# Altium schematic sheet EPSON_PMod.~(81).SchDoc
size A4
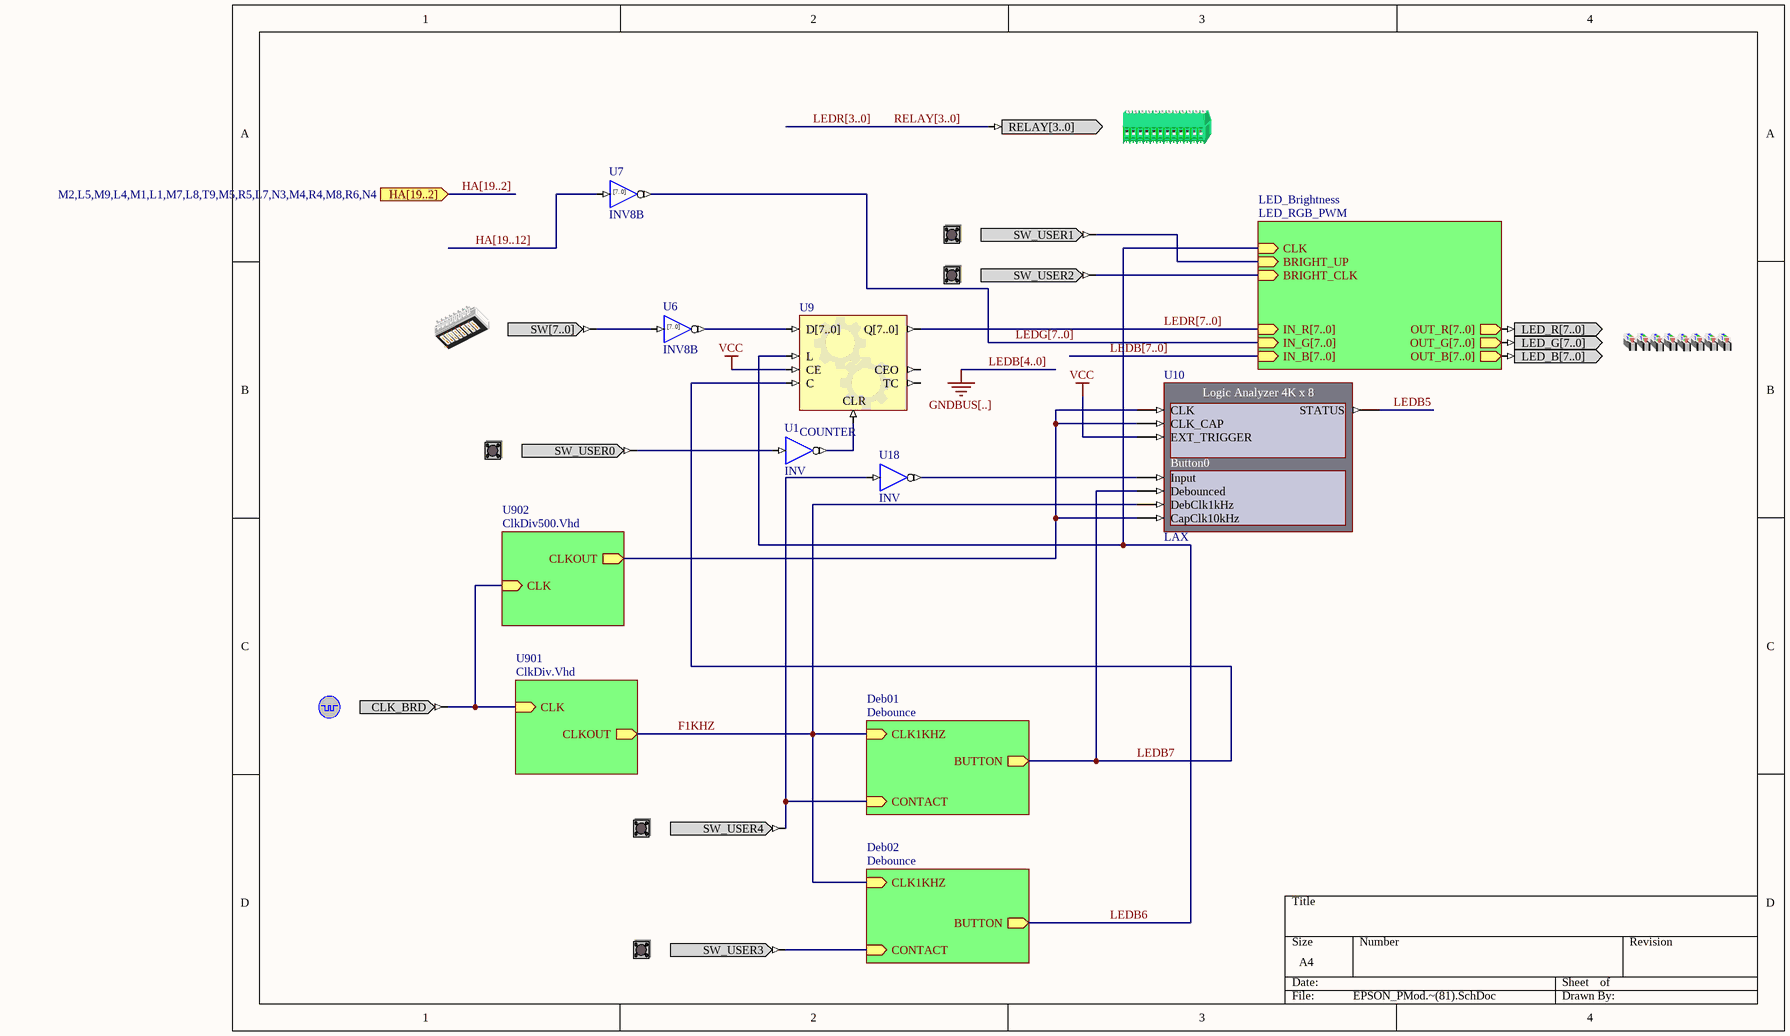
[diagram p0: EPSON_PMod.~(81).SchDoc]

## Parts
(Parts that share a designator on the sheet are numbered #1, #2 ... from top to bottom, then left to right.)
?#1  RELAYCNTR  (value not drawn)
?#2  USER_BUTTON1  (value not drawn)
?#3  USER_BUTTON2  (value not drawn)
?#4  DIPSWITCH  (value not drawn)
?#5  LEDS_RGB  (value not drawn)
?#6  USER_BUTTON0  (value not drawn)
?#7  CLOCK_BOARD  (value not drawn)
?#8  USER_BUTTON4  (value not drawn)
?#9  USER_BUTTON3  (value not drawn)
U1  INV
U6  INV8B
U7  INV8B
U9  COUNTER
U10  LAX
U18  INV

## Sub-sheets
Deb01 = Debounce: CONTACT (in), BUTTON (out), CLK1KHZ (in)
Deb02 = Debounce: CONTACT (in), BUTTON (out), CLK1KHZ (in)
LED_Brightness = LED_RGB_PWM: IN_R[7..0] (in), IN_G[7..0] (in), IN_B[7..0] (in), OUT_R[7..0] (out), OUT_G[7..0] (out), OUT_B[7..0] (out), CLK (in), BRIGHT_UP (in), BRIGHT_CLK (in)
U901 = ClkDiv.Vhd: CLK (in), CLKOUT (out)
U902 = ClkDiv500.Vhd: CLK (in), CLKOUT (out)

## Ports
HA[19..2] (in, see M2,L5,M9,L4,M1,L1,M7,L8,T9,M5,R5,L7,N3,M4,R4,M8,R6,N4)

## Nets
GND_BUS[3..0]: U10.Set0_Spare[3..0]
VCC: U9.CE U10.EXT_TRIGGER
F1KHZ: U10.DebClk1kHz ; sheet U901/CLKOUT, sheet Deb01/CLK1KHZ, sheet Deb02/CLK1KHZ
LEDB5: U10.STATUS
LEDB6: U9.L ; sheet Deb02/BUTTON, sheet LED_Brightness/CLK
LEDB7: U9.C U10.Debounced ; sheet Deb01/BUTTON
Net?#2_SW_USER1: ?#2.SW_USER1 ; sheet LED_Brightness/BRIGHT_UP
Net?#3_SW_USER2: ?#3.SW_USER2 ; sheet LED_Brightness/BRIGHT_CLK
Net?#6_SW_USER0: ?#6.SW_USER0 U1.I
Net?#7_CLK_BRD: ?#7.CLK_BRD ; sheet U901/CLK, sheet U902/CLK
Net?#8_SW_USER4: ?#8.SW_USER4 U18.I ; sheet Deb01/CONTACT
Net?#9_SW_USER3: ?#9.SW_USER3 ; sheet Deb02/CONTACT
NetU1_O: U1.O U9.CLR
NetU10_CapClk10kHz: U10.CapClk10kHz U10.CLK U10.CLK_CAP ; sheet U902/CLKOUT
NetU10_Input: U10.Input U18.O

Not connected (* = marked no-connect by the designer): ?#1 RELAY[3..0]; ?#4 SW[7..0]; ?#5 LED_B[7..0] LED_G[7..0] LED_R[7..0]; U6 I[7..0] O[7..0]; U7 I[7..0] O[7..0]; U9 CEO D[7..0] Q[7..0] TC

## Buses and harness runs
bus HA[19..2] = port HA[19..2]
bus HA[19..12]
bus LEDB[4..0]
bus LEDB[7..0] = sheet LED_Brightness/IN_B[7..0]
bus LEDG[7..0] = sheet LED_Brightness/IN_G[7..0]
bus LEDR[3..0] = RELAY[3..0]
bus LEDR[7..0] = sheet LED_Brightness/IN_R[7..0]

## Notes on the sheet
- Labels drawn without touching a wire or pin: GNDBUS[..]

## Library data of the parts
?#1 = RELAYCNTR: RELAY; PortComponent: True
?#2 = USER_BUTTON1: Generic User Button; PortComponent: True
?#3 = USER_BUTTON2: Generic User Button; PortComponent: True
?#4 = DIPSWITCH: 8-Way Dip-Switch; PortComponent: True
?#5 = LEDS_RGB: LEDS RGB; PortComponent: True
?#6 = USER_BUTTON0: Generic User Button; PortComponent: True
?#7 = CLOCK_BOARD: Global System Clock Supply; PortComponent: True
?#8 = USER_BUTTON4: Generic User Button; PortComponent: True
?#9 = USER_BUTTON3: Generic User Button; PortComponent: True
U1 U18 = INV: Inverter; FunctionalClass: Logic Primitive; ArchiveName: GENERIC; VHDLIB_SIM: GENERIC_LIB
U6 U7 = INV8B: 8-Bit Inverter, Bus Version; XilinxEquivalent: INV8; FunctionalClass: Logic Primitive; SubClass: INV; PortSize: 8; ArchiveName: GENERIC; VHDLIB_SIM: GENERIC_LIB
U9 = COUNTER: Configurable Counter; ConfiguratorName: GENERIC_COUNTER; ConfigurationParameters: {}Version[1.0]{}Type[Binary]{}SyncReset[False]{}NegativeClockEdge[False]{}FixedDirection[True]{}IsIncrement[True]{}SignalWidth[8]{}MaxValue[255]{}BusOutput[True]{}Loadable[True]{}BusInput[True]{}
U10 = LAX: Configurable Logic Analyzer; NEXUS_CORE: Instrument; NEXUS_JTAG_DEVICE: True; NEXUS_JTAG_ORDER: 0; ConfiguratorName: LogicAnalyser; ConfigurationParameters: {}Version[1.0]{}CaptureWidth[8]{}MemorySize[4K]{}ExtAddrWidth[10]{}Set0[Button0]{}Set0_Signal0[Input]{}Style_Set0_Signal0[Dark Grey]{}Set0_Signal1[Debounced]{}Style_Set0_Signal1[Dark Pink]{}Set0_Signal2[DebClk1kHz]{}Style_Set0_Signal2[Orange]{}Set0_Signal3[CapClk10kHz]{}Style_Set0_Signal3[Green]{}ConnectSpareToGND[True]{}; ChildModel1: LAX_CFG8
